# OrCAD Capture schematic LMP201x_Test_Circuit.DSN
size A; title: LMP2011 Single/LMP2012 Dual High Precision, Rail-to-Rail; rev: 1.2; note: Datasheet: SNOSA71L  EVM: N/A
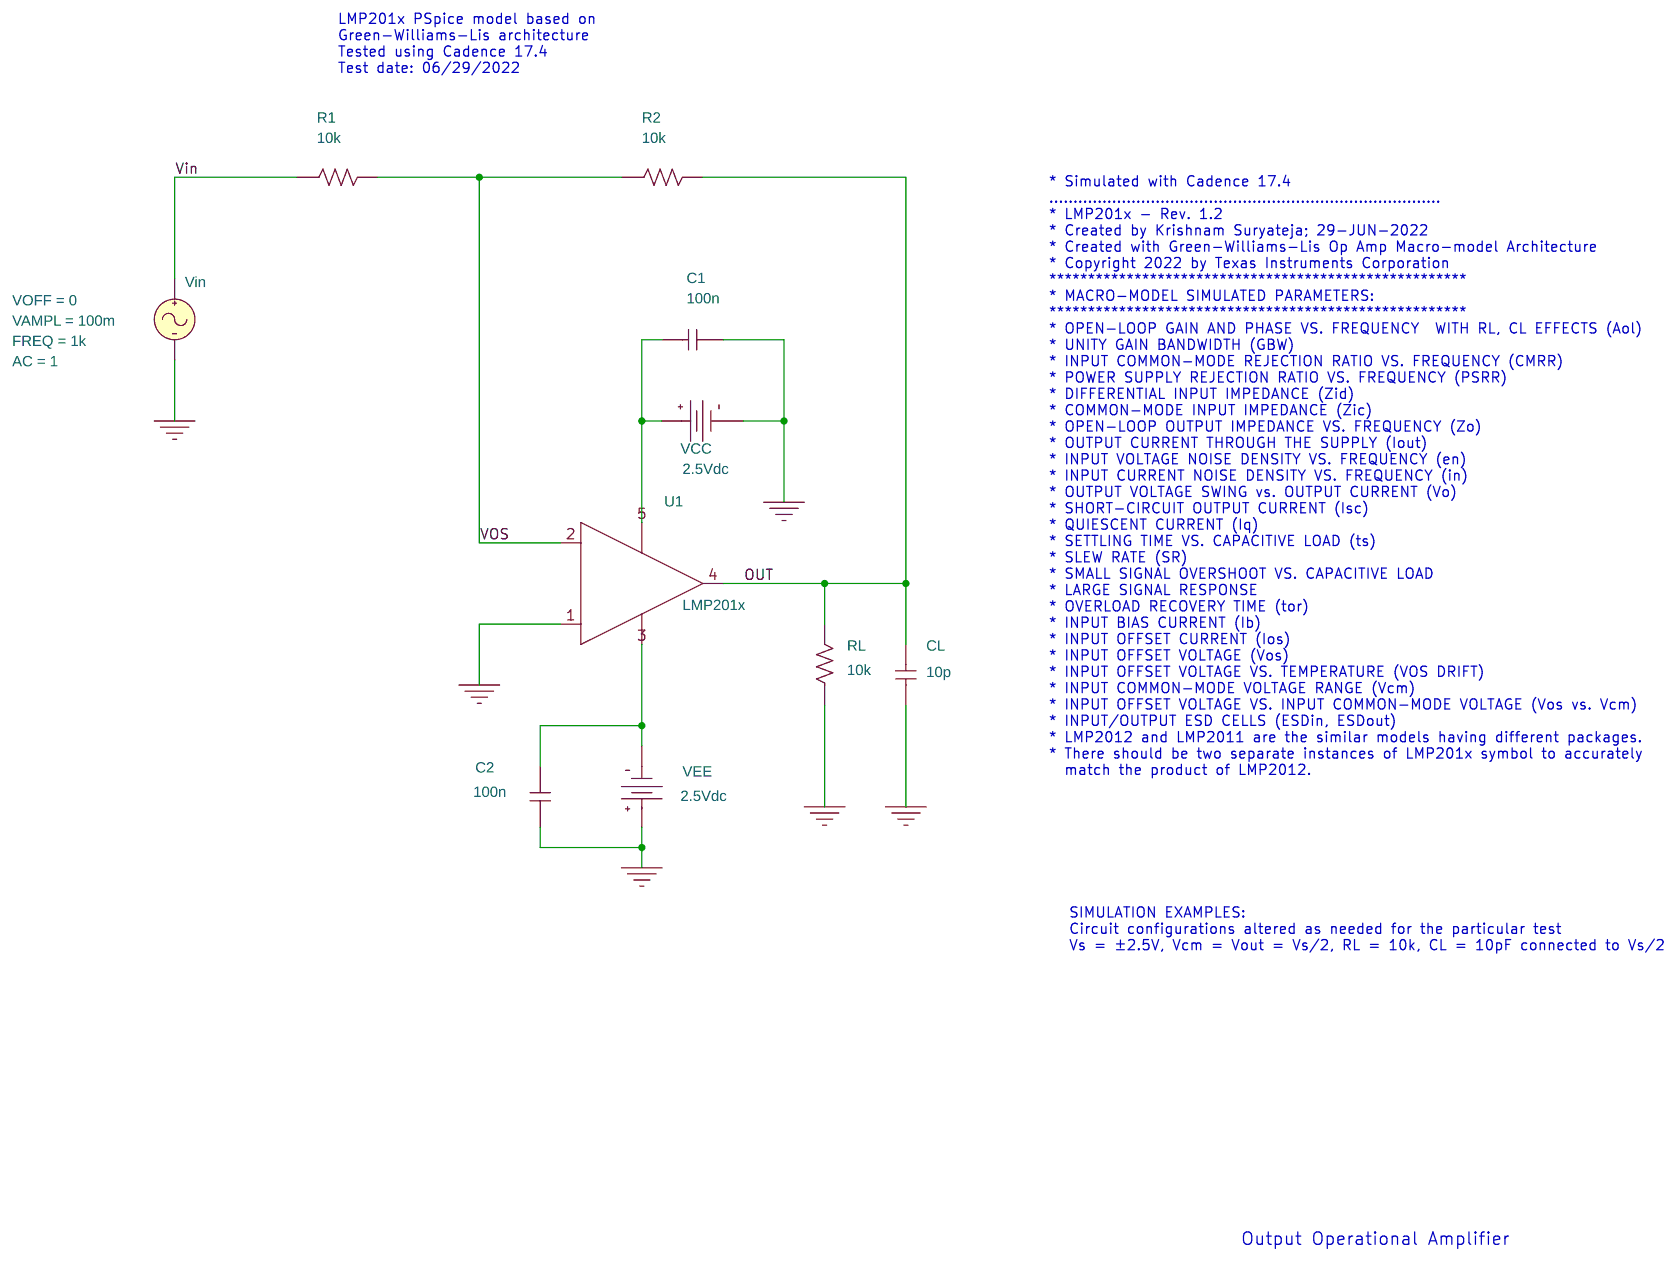
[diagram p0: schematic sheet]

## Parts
C1  100n  [cap196]
C2  100n  [cap196]
CL  10p  [cap196]
R1  10k  [AXRC05]
R2  10k  [AXRC05]
RL  10k  [AXRC05]
U1  LMP201x
VCC  VDC
VEE  VDC
Vin  VSIN

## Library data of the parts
C1 C2 CL = C
R1 R2 RL = R
U1 = LMP201x
VCC VEE = VDC: DC: 2.5Vdc
Vin = VSIN: AC: 1; FREQ: 1k; VAMPL: 100m; VOFF: 0

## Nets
Vin: R1.1 Vin.1(+)
0: C1.2 C2.1 CL.2 RL.1 U1.1(+) VCC.1(-) VEE.0(+) Vin.2(-)
OUT: CL.1 R2.2 RL.2 U1.4(OUT)
VOS: R1.2 R2.1 U1.2(-)
N27303: C1.1 U1.5(V+) VCC.0(+)
N27354: C2.2 U1.3(V-) VEE.1(-)

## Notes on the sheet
- LMP201x PSpice model based on
  Green-Williams-Lis architecture
  Tested using Cadence 17.4
  Test date: 06/29/2022
- * Simulated with Cadence 17.4
  .................................................................................
  * LMP201x - Rev. 1.2
  * Created by Krishnam Suryateja; 29-JUN-2022
  * Created with Green-Williams-Lis Op Amp Macro-model Architecture
  * Copyright 2022 by Texas Instruments Corporation
  ******************************************************
  * MACRO-MODEL SIMULATED PARAMETERS:
  ******************************************************
  * OPEN-LOOP GAIN AND PHASE VS. FREQUENCY  WITH RL, CL EFFECTS (Aol)
  * UNITY GAIN BANDWIDTH (GBW)
  * INPUT COMMON-MODE REJECTION RATIO VS. FREQUENCY (CMRR)
  * POWER SUPPLY REJECTION RATIO VS. FREQUENCY (PSRR)
  * DIFFERENTIAL INPUT IMPEDANCE (Zid)
  * COMMON-MODE INPUT IMPEDANCE (Zic)
  * OPEN-LOOP OUTPUT IMPEDANCE VS. FREQUENCY (Zo)
  * OUTPUT CURRENT THROUGH THE SUPPLY (Iout)
  * INPUT VOLTAGE NOISE DENSITY VS. FREQUENCY (en)
  * INPUT CURRENT NOISE DENSITY VS. FREQUENCY (in)
  * OUTPUT VOLTAGE SWING vs. OUTPUT CURRENT (Vo)
  * SHORT-CIRCUIT OUTPUT CURRENT (Isc)
  * QUIESCENT CURRENT (Iq)
  * SETTLING TIME VS. CAPACITIVE LOAD (ts)
  * SLEW RATE (SR)
  * SMALL SIGNAL OVERSHOOT VS. CAPACITIVE LOAD
  * LARGE SIGNAL RESPONSE
  * OVERLOAD RECOVERY TIME (tor)
  * INPUT BIAS CURRENT (Ib)
  * INPUT OFFSET CURRENT (Ios)
  * INPUT OFFSET VOLTAGE (Vos)
  * INPUT OFFSET VOLTAGE VS. TEMPERATURE (VOS DRIFT)
  * INPUT COMMON-MODE VOLTAGE RANGE (Vcm)
  * INPUT OFFSET VOLTAGE VS. INPUT COMMON-MODE VOLTAGE (Vos vs. Vcm)
  * INPUT/OUTPUT ESD CELLS (ESDin, ESDout)
  * LMP2012 and LMP2011 are the similar models having different packages.
  * There should be two separate instances of LMP201x symbol to accurately
    match the product of LMP2012.
- SIMULATION EXAMPLES:
  Circuit configurations altered as needed for the particular test
  Vs = ±2.5V, Vcm = Vout = Vs/2, RL = 10k, CL = 10pF connected to Vs/2
- Output Operational Amplifier
